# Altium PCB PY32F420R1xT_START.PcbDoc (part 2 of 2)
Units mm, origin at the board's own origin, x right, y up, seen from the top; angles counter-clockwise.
Board outline 45 x 98.2 mm, 2 copper layers (Top Layer, Bottom Layer), stack 0.533 mm thick; 144 components, 163 nets, 571 pads, 318 vias.
Unrouted connection lines stored in the file: 5.
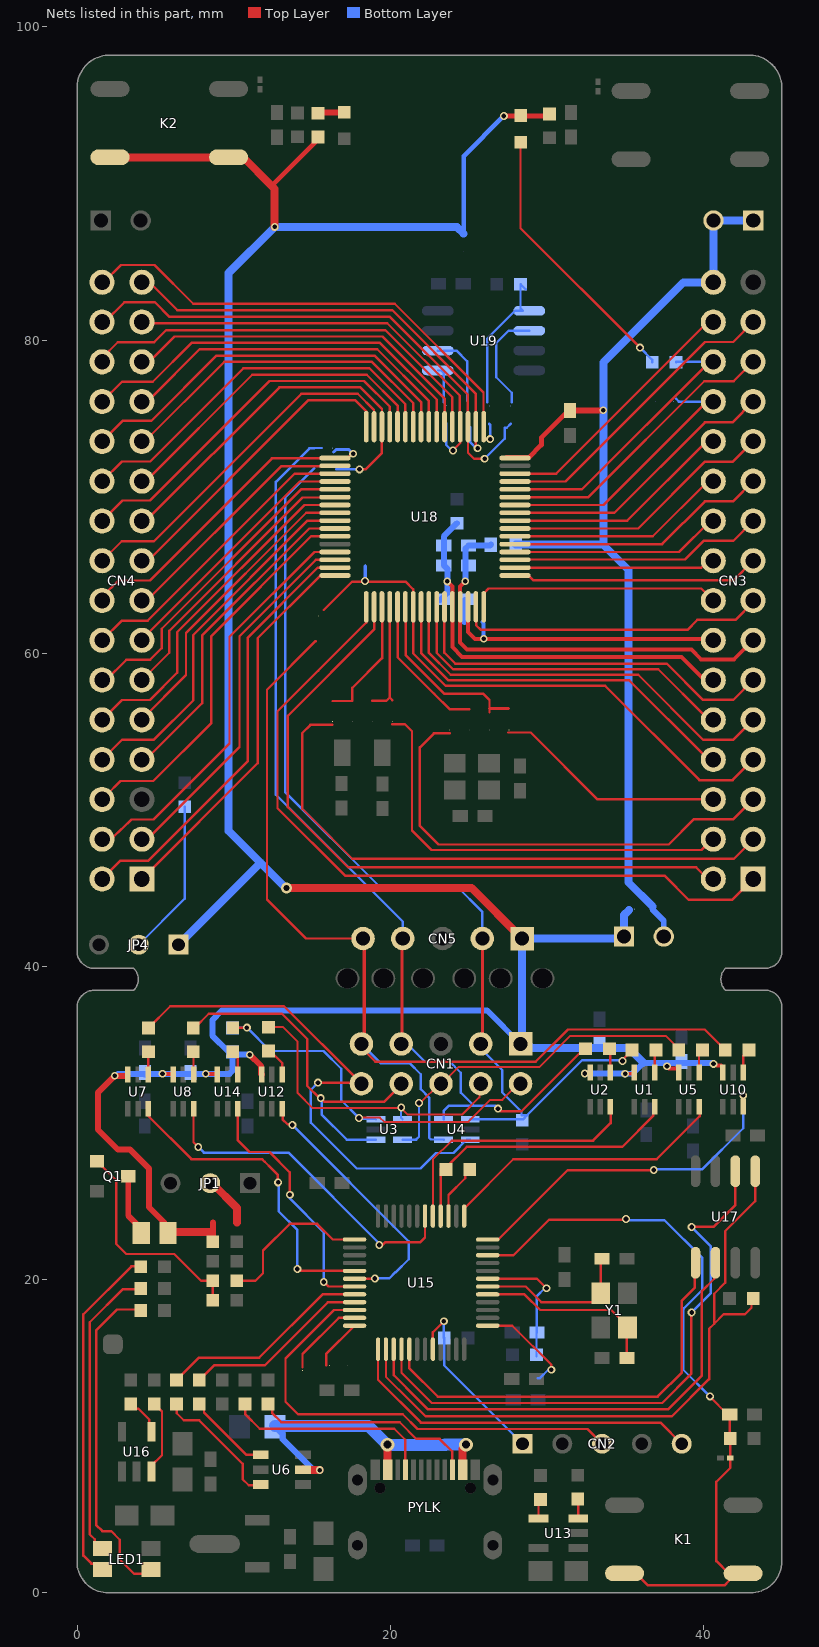
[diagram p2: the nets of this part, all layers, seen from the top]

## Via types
v1: diameter 0.5, hole 0.3, Top Layer to Bottom Layer, 156 vias
v2: diameter 0.5, hole 0.3, Top Layer to Bottom Layer, tented both sides, 134 vias
v3: diameter 0.559, hole 0.305, Top Layer to Bottom Layer, 14 vias
v4: diameter 0.889, hole 0.508, Top Layer to Bottom Layer, tented both sides, 8 vias
v5: diameter 0.762, hole 0.381, Top Layer to Bottom Layer, tented both sides, 2 vias
v6: diameter 1.016, hole 0.508, Top Layer to Bottom Layer, tented both sides, 2 vias
v7: diameter 0.61, hole 0.305, Top Layer to Bottom Layer, tented both sides, 1 vias
v8: diameter 0.711, hole 0.381, Top Layer to Bottom Layer, 1 vias

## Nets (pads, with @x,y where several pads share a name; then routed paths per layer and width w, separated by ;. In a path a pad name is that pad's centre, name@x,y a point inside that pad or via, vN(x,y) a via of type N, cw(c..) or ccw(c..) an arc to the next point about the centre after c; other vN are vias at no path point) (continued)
NetC36_2: C36.2 R63.2 | length 1.4
  Bottom Layer w0.381: R63.2@24.739,62.001 24.765,62.027 C36.2@24.765,63.398
NetJP4_2: JP4.2 R55.1 | length 10
  Bottom Layer w0.152: JP4.2@3.937,41.391 6.871,44.325 R55.1@6.871,50.202
NetLED1_2: LED1.2 R9.1 | length 21.5
  Top Layer w0.152: R9.1@4.064,18.034 4.005,18.093 2.548,18.093 1.219,16.764 1.219,4.343 1.621,3.942 2.181,3.942 2.731,3.392 2.731,2.138 3.653,1.216 4.447,1.216 LED1.2@4.725,1.494
NetLED1_3: LED1.3 R6.1 | length 22.5
  Top Layer w0.152: LED1.3@1.125,1.486 LED1.3@1.498,1.113 ; LED1.3@1.625,1.494 1.252,1.867 0.917,1.867 0.406,2.378 0.406,17.789 3.469,20.852 4.04,20.852 R6.1@4.064,20.828
NetLED1_4: LED1.4 R4.1 | length 19.2
  Top Layer w0.152: LED1.4@1.439,2.502 1.127,2.814 1.127,3.422 0.813,3.736 0.813,17.281 2.931,19.399 4.032,19.399 R4.1@4.064,19.431
NetLED_PB2_2: LED_PB2.2 R45.1 | length 17.5
  Top Layer w0.152: LED_PB2.2@28.321,92.634 28.321,87.14 v1(35.947,79.514)
  Bottom Layer w0.152: v1(35.947,79.514) 36.728,78.733 R45.1@36.728,78.588
NetLED_VDD*_1: LED_VDD*.1 R40.1 | length 1.7
  Top Layer w0.152: R40.1@15.392,94.488 R40.1@15.443,94.539
  Top Layer w0.381: R40.1@15.443,94.539 LED_VDD*.1@17.069,94.539
NetPYLK_A5: PYLK.A5 R1.2 | length 13.5
  Top Layer w0.152: R1.2@10.731,12.065 10.731,11.425 11.672,10.485 20.259,10.485 20.964,9.78 20.964,7.888 PYLK.A5@20.98,7.871
NetPYLK_B5: PYLK.B5 R3.1 | length 14.4
  Top Layer w0.152: R3.1@12.192,12.065 12.454,11.803 12.454,11.489 13.052,10.891 20.602,10.891 21.658,9.836 23.153,9.836 23.957,9.033 23.957,7.895 PYLK.B5@23.98,7.871
NetQ1_1: Q1.1 R19.1 R20.2 | length 14.2
  Top Layer w0.152: Q1.1@1.27,27.554 1.32,27.554 1.618,27.256 1.618,27.209 2.501,26.327 2.501,22.284 3.146,21.639 6.209,21.639 7.915,19.933 R19.1@8.675,19.933 ; R20.2@8.675,18.691 R19.1@8.675,19.933
NetQ1_3: Q1.3 R15.1 | length 4.2
  Top Layer w0.152: Q1.3@3.187,26.521 Q1.3@3.27,26.604 ; R15.1@4.103,22.987 R15.1@4.103,23.137
  Top Layer w0.381: Q1.3@3.27,26.604 3.27,24.086 4.103,23.253 R15.1@4.103,22.987
NetR2_1: R2.1 U1.4 | length 1.5
  Top Layer w0.152: U1.4@36.887,33.231 36.887,34.595 R2.1@36.962,34.671
NetR7_1: R7.1 U2.4 | length 1.5
  Top Layer w0.152: R7.1@33.987,34.671 34.056,34.602 U2.4@34.056,33.231
NetR10_1: R10.1 U5.4 | length 1.5
  Top Layer w0.152: U5.4@39.717,33.231 39.717,34.45 R10.1@39.938,34.671
NetR11_1: R11.1 U6.3 | length 8.5
  Top Layer w0.152: R11.1@6.35,12.065 6.37,12.045 6.37,11.473 6.818,11.025 7.793,11.025 10.572,8.245 10.572,7.261 10.963,6.87 11.677,6.87 U6.3@11.723,6.916
NetR12_1: R12.1 U6.1 | length 5.8
  Top Layer w0.152: R12.1@7.842,12.192 8.106,11.928 8.106,11.523 10.82,8.809 U6.1@11.988,8.809
NetR13_1: R13.1 U7.4 | length 1.5
  Top Layer w0.152: R13.1@4.408,34.544 4.55,34.402 U7.4@4.55,33.104
NetR14_1: R14.1 U8.4 | length 1.5
  Top Layer w0.152: R14.1@7.136,34.544 R14.1@7.387,34.294 ; U8.4@7.439,33.104 R14.1@7.439,34.293
NetR18_1: R18.1 U10.4 | length 1.6
  Top Layer w0.152: U10.4@42.547,33.231 42.547,34.305 R18.1@42.913,34.671
NetR22_1: R22.1 U12.4 | length 1.9
  Top Layer w0.152: R22.1@12.233,34.598 12.335,34.598 13.099,33.833 U12.4@13.099,33.104
NetR24_2: R24.2 U13.4 | length 1.3
  Top Layer w0.152: U13.4@29.464,4.763 29.464,5.842 R24.2@29.591,5.969
NetR25_2: R25.2 U13.3 | length 1.2
  Top Layer w0.152: U13.3@32.004,4.763 R25.2@32.004,5.969
NetR26_1: R26.1 U14.4 | length 1.6
  Top Layer w0.152: R26.1@9.936,34.562 10.269,34.229 U14.4@10.269,33.104
NetR27_2: R27.2 U15.1 | length 6.5
  Top Layer w0.152: U15.1@26.221,17.062 27.792,17.062 30.288,14.566 v1(30.288,14.246)
  Bottom Layer w0.152: 29.422,13.712 29.556,13.712 30.09,14.246 v1(30.288,14.246)
NetR29_2: R29.2 U16.4 | length 2.4
  Top Layer w0.152: R29.2@3.429,12.065 3.734,11.76 3.923,11.76 4.61,11.073 4.61,10.439 U16.4@4.763,10.287
NetR30_2: R30.2 U16.3 | length 4.8
  Top Layer w0.152: U16.3@4.763,7.747 4.763,8.128 5.424,8.79 5.424,11.574 5.258,11.741 5.258,11.76 R30.2@4.953,12.065
NetR31_1: R31.1 U15.36 | length 3.3
  Top Layer w0.152: 15.906,14.522 15.906,15.247 U15.36@17.721,17.062
NetR33_1: R33.1 U15.35 | length 5.1
  Top Layer w0.152: 14.401,14.412 14.401,15.25 16.713,17.562 U15.35@17.721,17.562
NetR44_1: R44.1 R46.1 U19.1 | length 9.3
  Bottom Layer w0.152: 26.187,76.023 26.187,80.08 27.972,81.864 28.473,81.864 28.321,82.017 R44.1@28.321,83.566 ; R44.1@28.325,83.557 R44.1@28.651,83.231
NetR47_1: R47.1 U19.2 | length 6.6
  Bottom Layer w0.152: 27.762,76.022 27.762,76.632 26.772,77.622 26.772,79.807 27.559,80.594 U19.2@28.88,80.594
NetR48_2: R48.2 U19.6 | length 4.7
  Bottom Layer w0.152: U19.6@23.038,79.324 24.232,79.324 24.917,78.638 24.917,76.124
NetR49_2: R49.2 U19.5 | length 2.3
  Bottom Layer w0.152: U19.5@23.038,78.054 23.266,78.054 23.419,77.901 23.419,76.022
OSC_32INa: R38.2 R57.2 U18.3 | length 8.1
  Top Layer w0.152: 16.312,56.951 17.585,56.951 17.585,57.793 19.482,59.69 19.482,62.952 U18.3@19.468,62.967
OSC_32OUTa: R39.2 R59.2 U18.4 | length 7.2
  Top Layer w0.152: 18.847,56.964 19.757,56.964 19.965,57.173 ; U18.4@19.965,62.967 19.965,57.173 ; 20.137,57.001 19.965,57.173
OSC_INa: R41.2 R53.2 U18.5 | length 9.2
  Top Layer w0.152: U18.5@20.469,63.015 20.469,59.745 22.811,57.403 23.806,56.408 23.817,56.418 25.043,56.418
OSC_OUTa: R42.2 R56.2 U18.6 | length 11.7
  Top Layer w0.152: U18.6@20.98,63.008 20.98,59.881 23.455,57.405 25.954,57.405 26.34,57.018 R56.2@26.34,56.236
  Top Layer w0.203: 26.341,56.469 26.347,56.463 27.533,56.463
PA0: CN3.14 R63.1 U18.14 | length 18.6
  Top Layer w0.254: U18.14@24.969,62.952 24.969,61.342 25.411,60.9 40.557,60.9 CN3.14@40.63,60.827
  Bottom Layer w0.254: R63.1@25.876,62.001 25.97,61.908 v1(25.97,60.925)
PA1: CN3.15 U18.15 | length 19.8
  Top Layer w0.152: U18.15@25.468,62.967 25.486,62.948 25.486,61.791 25.786,61.492 38.972,61.492 39.609,62.128 42.041,62.128 43.17,63.257 CN3.15@43.17,63.367
PA2: CN3.16 U18.16 | length 16
  Top Layer w0.152: U18.16@25.968,62.967 25.968,63.821 26.282,64.135 39.862,64.135 CN3.16@40.63,63.367
PA3: CN3.17 U18.17 | length 15.9
  Top Layer w0.152: U18.17@27.967,64.966 28.836,64.966 29.152,64.65 41.913,64.65 CN3.17@43.17,65.907
PA4: CN3.20 U18.20 | length 13.2
  Top Layer w0.152: U18.20@28.271,66.467 38.448,66.467 40.429,68.447 CN3.20@40.63,68.447
PA5: CN3.21 U18.21 | length 16.6
  Top Layer w0.152: U18.21@28.271,66.966 37.363,66.966 40.094,69.698 41.88,69.698 CN3.21@43.17,70.987
PA6: CN3.22 U18.22 | length 13.8
  Top Layer w0.152: U18.22@28.271,67.467 36.761,67.467 40.282,70.987 CN3.22@40.63,70.987
PA7: CN3.23 U18.23 | length 17.2
  Top Layer w0.152: U18.23@28.271,67.966 35.834,67.966 40.106,72.238 41.88,72.238 CN3.23@43.17,73.527
PA8: CN4.24 U18.41 | length 25.4
  Top Layer w0.152: CN4.24@1.604,73.527 2.914,74.838 4.74,74.838 8.909,79.007 19.005,79.007 21.973,76.039 21.973,74.471 U18.41@21.968,74.466
PA9: CN4.23 U18.42 | length 22.1
  Top Layer w0.152: CN4.23@4.141,73.527 4.232,73.437 9.396,78.6 18.837,78.6 21.476,75.961 21.476,74.475 U18.42@21.468,74.466
PA10: CN4.22 U18.43 | length 24.8
  Top Layer w0.152: CN4.22@1.604,70.987 2.862,72.246 4.676,72.246 10.624,78.194 18.668,78.194 20.953,75.909 20.953,74.481 U18.43@20.968,74.466 ; U18.43@20.94,74.422 U18.43@20.976,74.458
PA11: CN4.21 U18.44 | length 21.7
  Top Layer w0.152: CN4.21@4.409,70.72 CN4.21@4.141,70.987 4.184,71.03 4.432,71.03 11.19,77.787 18.5,77.787 20.47,75.817 U18.44@20.47,74.498
PA12: CN4.20 U18.45 | length 24
  Top Layer w0.152: CN4.20@1.604,68.447 2.908,69.751 4.668,69.751 12.297,77.381 18.332,77.381 19.966,75.746 U18.45@19.966,74.466
PA13: CN4.19 R51.2 U18.46 | length 25.6
  Top Layer w0.152: CN4.19@4.141,68.447 4.163,68.469 4.414,68.469 12.92,76.975 18.092,76.975 19.474,75.592 U18.46@19.474,74.473 ; v2(18.034,71.743) 18.417,71.743 19.468,72.793 U18.46@19.468,74.466
  Bottom Layer w0.152: 16.547,71.743 v2(18.034,71.743)
PA14: CN4.16 R52.2 U18.49 | length 21.4
  Top Layer w0.152: CN4.16@1.604,63.367 1.604,63.608 2.64,64.645 4.65,64.645 12.446,72.441 15.149,72.441 ; 15.149,72.448 U18.49@15.915,72.448 ; U18.49@15.936,72.448 U18.49@16.468,72.448 ; U18.49@16.468,72.467 17.284,72.467 17.552,72.735 v1(17.629,72.735)
  Bottom Layer w0.203: 16.383,72.847 16.545,73.009 17.354,73.009 v1(17.629,72.735)
PA15: CN4.15 U18.50 | length 16.2
  Top Layer w0.152: CN4.15@4.141,63.367 4.455,63.367 13.022,71.933 15.82,71.933 15.835,71.948 16.753,71.948 U18.50@16.772,71.966
PB0: CN3.26 R58.2 U18.26 | length 17.6
  Top Layer w0.152: U18.26@27.949,69.448 U18.26@27.967,69.467 ; U18.26@28.271,69.467 33.627,69.467 40.228,76.067 CN3.26@40.63,76.067
  Bottom Layer w0.152: 38.258,76.247 38.413,76.092 ; 38.413,76.067 CN3.26@40.63,76.067
PB1: CN3.27 U18.27 | length 18.5
  Top Layer w0.152: U18.27@28.271,69.966 32.654,69.966 40.051,77.364 41.926,77.364 CN3.27@43.17,78.607
PB2: CN3.28 R45.2 U18.28 | length 18.1
  Top Layer w0.152: U18.28@28.271,70.467 32.24,70.467 40.38,78.607 CN3.28@40.63,78.607
  Bottom Layer w0.152: R45.2@38.252,78.588 38.272,78.607 CN3.28@40.63,78.607
PB3: CN4.10 U18.55 | length 22.1
  Top Layer w0.152: CN4.10@1.604,55.747 2.874,57.017 4.656,57.017 6.401,58.762 6.401,61.349 14.519,69.467 U18.55@16.468,69.467
PB4: CN4.9 U18.56 | length 19.7
  Top Layer w0.152: CN4.9@4.141,55.747 4.141,55.787 6.957,58.603 6.957,61.291 14.632,68.966 U18.56@16.772,68.966
PB5: CN4.8 U18.57 | length 23.9
  Top Layer w0.152: CN4.8@1.604,53.207 1.839,53.443 2.884,54.487 4.919,54.487 7.419,56.987 7.419,61.162 14.724,68.467 U18.57@16.772,68.467
PB6: CN4.7 U18.58 | length 21.3
  Top Layer w0.152: CN4.7@4.141,53.207 4.384,53.207 7.987,56.809 7.987,61.123 14.83,67.966 U18.58@16.772,67.966
PB7: CN4.6 U18.59 | length 25.4
  Top Layer w0.152: CN4.6@1.604,50.667 1.871,50.934 2.779,51.842 4.865,51.842 8.577,55.554 8.577,61.097 14.946,67.467 U18.59@16.772,67.467
PB8: CN4.4 U18.61 | length 26.7
  Top Layer w0.152: CN4.4@1.604,48.127 1.731,48.254 2.301,48.254 3.483,49.385 4.888,49.385 9.738,54.236 9.738,61.049 15.156,66.467 U18.61@16.772,66.467
PB9: CN4.3 U18.62 | length 24.2
  Top Layer w0.152: CN4.3@4.141,48.127 4.409,48.394 4.755,48.394 10.371,54.011 10.371,61.082 15.255,65.966 U18.62@16.772,65.966
PB10: CN3.29 U18.29 | length 19.1
  Top Layer w0.152: U18.29@28.271,70.966 31.19,70.966 40.101,79.877 41.9,79.877 CN3.29@43.17,81.147
PB11: CN3.30 U18.30 | length 16.4
  Top Layer w0.152: U18.30@28.271,71.467 30.598,71.467 40.278,81.147 CN3.30@40.63,81.147
PB12: CN4.32 R46.2 U18.33 | length 32.6
  Top Layer w0.152: CN4.32@1.604,83.687 1.712,83.687 2.816,84.792 4.949,84.792 7.423,82.318 20.292,82.318 25.952,76.658 25.952,74.482 U18.33@25.968,74.466 25.931,74.43 25.931,73.678 v1@26.373,73.678
  Bottom Layer w0.152: R46.2@26.315,74.644 26.38,74.579 v1(26.38,73.672)
PB13: CN4.31 R48.1 U18.34 | length 29.4
  Top Layer w0.152: CN4.31@4.141,83.687 4.345,83.484 4.832,83.484 6.405,81.911 20.124,81.911 25.45,76.585 25.45,74.483 U18.34@25.468,74.466 25.468,73.108 25.485,73.091 v1(25.582,73.091)
  Bottom Layer w0.152: 25.121,74.422 25.121,73.456 25.485,73.091 v1(25.582,73.091)
PB14: CN4.30 R47.2 U18.35 | length 34.2
  Top Layer w0.152: CN4.30@1.604,81.147 1.754,81.147 3.021,82.414 4.97,82.414 5.906,81.478 19.982,81.478 24.959,76.502 U18.35@24.959,74.475 ; U18.35@24.968,74.466 24.968,72.806 25.355,72.42 v1(26.026,72.42)
  Bottom Layer w0.152: v1(26.026,72.42) 27.305,73.699 27.305,74.397 27.439,74.397 R47.2@27.687,74.644
PB15: CN4.29 R49.1 U18.36 | length 27.9
  Top Layer w0.152: CN4.29@4.141,81.147 4.217,81.072 19.814,81.072 24.447,76.438 24.447,75.405 24.449,75.403 24.449,74.485 U18.36@24.468,74.466 24.468,73.429 24.003,72.964 v1(24.003,72.944)
  Bottom Layer w0.152: R49.1@23.571,74.676 23.571,73.305 23.931,72.944 v1(24.003,72.944)
PC0: CN3.8 U18.8 | length 24.4
  Top Layer w0.152: U18.8@21.97,62.964 21.97,60.013 23.714,58.27 35.265,58.27 40.129,53.405 40.432,53.405 CN3.8@40.63,53.207
PC1: CN3.9 U18.9 | length 26.4
  Top Layer w0.152: U18.9@22.468,62.905 22.468,60.019 23.861,58.625 35.832,58.625 39.989,54.469 41.891,54.469 CN3.9@43.17,55.747
PC2: CN3.10 U18.10 | length 22.3
  Top Layer w0.152: U18.10@22.968,62.926 22.968,60.021 24.008,58.981 37.116,58.981 40.162,55.935 40.442,55.935 CN3.10@40.63,55.747
PC3: CN3.11 U18.11 | length 24.4
  Top Layer w0.152: U18.11@23.457,62.956 23.457,60.035 24.156,59.336 37.656,59.336 39.973,57.019 41.902,57.019 CN3.11@43.17,58.287
PC4: CN3.24 U18.24 | length 14.5
  Top Layer w0.152: U18.24@28.271,68.467 35.131,68.467 40.192,73.527 CN3.24@40.63,73.527
PC5: CN3.25 U18.25 | length 17.8
  Top Layer w0.152: U18.25@28.271,68.966 34.315,68.966 40.091,74.742 41.845,74.742 CN3.25@43.17,76.067
PC6: CN4.28 U18.37 | length 27
  Top Layer w0.152: CN4.28@1.604,78.607 1.604,78.861 2.599,79.856 4.919,79.856 5.695,80.632 19.679,80.632 23.968,76.343 U18.37@23.968,74.466
PC7: CN4.27 U18.38 | length 23.4
  Top Layer w0.152: CN4.27@4.141,78.607 4.602,78.607 6.22,80.226 19.51,80.226 23.469,76.267 U18.38@23.469,74.468
PC8: CN4.26 U18.39 | length 26.1
  Top Layer w0.152: CN4.26@1.604,76.067 2.876,77.339 4.837,77.339 7.317,79.819 19.342,79.819 22.967,76.195 U18.39@22.967,74.467
PC9: CN4.25 U18.40 | length 22.7
  Top Layer w0.152: CN4.25@4.141,76.067 4.378,76.303 4.716,76.303 7.825,79.413 19.174,79.413 22.449,76.138 22.449,75.403 22.449,74.485 U18.40@22.468,74.466
PC10: CN4.14 U18.51 | length 19.3
  Top Layer w0.152: CN4.14@1.604,60.827 2.863,62.086 4.518,62.086 13.898,71.467 U18.51@16.468,71.467
PC11: CN4.13 U18.52 | length 16.6
  Top Layer w0.152: CN4.13@4.141,60.827 4.141,60.89 14.219,70.967 U18.52@16.467,70.967
PC12: CN4.12 U18.53 | length 20.9
  Top Layer w0.152: CN4.12@1.604,58.287 1.853,58.287 3.153,59.587 4.664,59.587 5.406,60.329 5.406,61.562 14.308,70.464 U18.53@16.769,70.464
PC13: CN3.2 U18.2 | length 44.1
  Top Layer w0.152: U18.2@18.972,62.891 18.972,61.517 13.455,56 13.455,50.177 17.301,46.331 39.534,46.331 40.278,45.587 CN3.2@40.63,45.587
PC14: CN3.3 R38.1 | length 37.6
  Top Layer w0.152: 16.312,55.427 14.9,55.427 14.376,54.904 14.376,50.071 17.575,46.873 41.952,46.873 43.17,48.091 CN3.3@43.17,48.127
PC15: CN3.4 R39.1 | length 27.8
  Top Layer w0.152: 20.137,55.477 20.929,55.477 21.387,55.019 21.387,48.685 22.639,47.433 39.869,47.433 40.564,48.127 CN3.4@40.63,48.127
PD0: CN3.5 R41.1 | length 30.3
  Top Layer w0.152: 23.806,54.884 22.788,54.884 21.89,53.986 21.89,48.978 23.08,47.788 26.999,47.788 37.781,47.788 39.403,49.41 41.913,49.41 CN3.5@43.17,50.667
PD1: CN3.6 R42.1 | length 14.9
  Top Layer w0.152: 27.533,54.939 28.972,54.939 33.243,50.667 CN3.6@40.63,50.667
PD2: CN4.11 U18.54 | length 18.3
  Top Layer w0.152: CN4.11@4.144,58.287 4.256,58.399 5.885,60.029 5.885,61.43 14.402,69.947 15.834,69.947 15.835,69.948 16.753,69.948 U18.54@16.772,69.966
PD4: CN3.18 U18.18 | length 12.5
  Top Layer w0.152: U18.18@28.274,65.464 39.848,65.464 40.292,65.907 CN3.18@40.63,65.907
PD5: CN3.19 U18.19 | length 15.9
  Top Layer w0.152: U18.19@28.271,65.966 28.29,65.985 38.811,65.985 40.003,67.177 41.9,67.177 CN3.19@43.17,68.447
PD6: CN4.18 U18.47 | length 23.3
  Top Layer w0.152: CN4.18@1.604,65.907 2.851,67.154 4.914,67.154 14.328,76.568 17.923,76.568 18.964,75.528 U18.47@18.964,74.46
PD7: CN4.17 U18.48 | length 19.8
  Top Layer w0.152: CN4.17@4.141,65.907 4.529,65.907 14.783,76.162 17.755,76.162 18.478,75.439 U18.48@18.478,74.547
PD8: CN4.2 U18.63 | length 28
  Top Layer w0.152: CN4.2@1.604,45.587 2.779,46.762 4.558,46.762 10.912,53.116 10.912,61.005 15.374,65.467 U18.63@16.772,65.467
PD9: CN4.1 U18.64 | length 25.3
  Top Layer w0.152: CN4.1@4.141,45.587 11.533,52.979 11.533,60.958 15.541,64.966 U18.64@16.772,64.966
PD10: CN3.1 U18.1 | length 48.6
  Top Layer w0.152: U18.1@18.466,62.965 18.466,61.956 15.392,58.882 12.802,56.292 12.802,50.107 17.111,45.798 37.512,45.798 39.06,44.249 41.832,44.249 CN3.1@43.17,45.587
PD11: CN3.7 R54.2 R62.2 U18.7 | length 37.3
  Top Layer w0.152: 15.759,62.76 17.57,64.571 20.973,64.571 21.468,64.076 U18.7@21.468,62.967 21.467,59.992 23.546,57.914 33.724,57.914 39.74,51.898 41.86,51.898 CN3.7@43.17,53.207
  Bottom Layer w0.203: v1(18.384,64.609) 18.4,64.625 18.4,65.549
PYLK_BOOT0: CN2.1 R28.1 U15.44 | length 12
  Top Layer w0.152: U15.44@22.721,15.562 22.721,16.639 v2(23.424,17.342)
  Bottom Layer w0.152: v2(23.424,17.342) 23.424,16.301 R28.1@23.444,16.281 23.444,14.529 CN2.1@28.448,9.525
PYLK_KEY: C6.2 K1.1 K1.2 R16.1 U11.1 U15.10 | length 47
  Top Layer w0.152: U15.10@26.221,21.562 27.867,21.562 30.136,23.83 35.006,23.83 v2(35.052,23.876) ; K1.2@34.964,1.245 35.693,1.245 36.462,0.476 41.335,0.476 41.631,0.772 41.631,0.877 K1.1@41.999,1.245 ; v2(40.411,12.548) 40.411,12.522 41.554,11.379 C6.2@41.656,11.379 ; C6.2@41.681,11.379 41.681,9.881 R16.1@41.707,9.855 41.714,9.848 U11.1@41.714,8.611 41.714,7.983 40.825,7.094 40.825,2.032 41.613,1.245 K1.1@41.999,1.245 ; K1.1@42.533,1.245 K1.1@41.999,1.245
  Bottom Layer w0.152: v2(35.052,23.876) 35.13,23.798 35.373,23.798 35.374,23.797 37.507,23.797 39.929,21.374 39.929,19.355 38.742,18.168 38.742,18.154 38.714,18.126 38.714,14.245 v2(40.411,12.548)
PYLK_NRST: C24.2 R36.1 U15.7 | length 8.7
  Top Layer w0.152: U15.7@26.221,20.062 29.372,20.062 v2(29.982,19.451)
  Bottom Layer w0.152: R36.1@29.34,15.113 29.34,16.612 C24.2@29.365,16.637 29.365,18.948 29.868,19.451 v2(29.982,19.451)
PYLK_OSCIN: C19.2 U15.5 Y1.3 | length 11.8
  Top Layer w0.152: U15.5@26.221,19.062 28.576,19.062 29.576,18.062 34.115,18.062 35.143,17.034 Y1.3@35.143,16.934 35.106,16.897 C19.2@35.106,14.986
PYLK_OSCOUT: C25.2 U15.6 Y1.1 | length 10.2
  Top Layer w0.152: U15.6@26.221,19.562 28.651,19.562 29.651,18.562 32.945,18.562 33.443,19.06 Y1.1@33.443,19.134 33.443,21.248 C25.2@33.531,21.336
PYLK_SPI_CS: R35.1 U15.38 U17.1 | length 42.4
  Top Layer w0.127: U15.38@19.721,15.562 19.721,13.808 21.277,12.252
  Top Layer w0.152: 21.277,12.252 22.249,11.28 37.986,11.28 40.358,13.652 40.358,16.863 40.685,17.19 ; R35.1@43.18,18.796 43.069,18.685 43.069,18.204 42.656,17.791 41.286,17.791 40.685,17.19 ; U17.1@43.307,26.924 43.307,25.019 41.394,23.106 41.394,19.812 40.685,19.103 40.685,17.19
PYLK_SPI_MISO: U15.40 U17.2 | length 37.5
  Top Layer w0.152: U15.40@20.721,15.562 20.721,14.054 22.652,12.123 37.363,12.123 39.215,13.975 39.215,17.879 v2(39.243,17.907) ; v2(39.243,23.368) 40.64,23.368 42.037,24.765 U17.2@42.037,26.924
  Bottom Layer w0.152: v2(39.243,17.907) 40.458,19.122 40.458,22.153 v2(39.243,23.368)
PYLK_SPI_MOSI: U15.41 U17.5 | length 27.4
  Top Layer w0.152: U15.41@21.221,15.562 21.221,14.338 23.029,12.53 37.069,12.53 38.622,14.082 38.622,18.671 39.45,19.499 39.45,21.035 U17.5@39.497,21.082
PYLK_SPI_SCK: U15.39 U17.6 | length 30.7
  Top Layer w0.152: U15.39@20.221,15.562 20.221,13.903 21.751,12.373 22.407,11.717 37.746,11.717 39.883,13.854 39.883,19.255 40.689,20.061 40.689,21.004 U17.6@40.767,21.082
SWD_SCK: CN2.5 U15.37 | length 23
  Top Layer w0.152: U15.37@19.221,15.562 19.221,13.608 21.958,10.871 34.722,10.871 37.262,10.871 CN2.5@38.608,9.525
SWD_SDA: CN2.3 U15.34 | length 29.8
  Top Layer w0.152: U15.34@17.721,18.062 16.411,18.062 13.311,14.962 13.311,12.21 14.111,11.41 20.796,11.41 21.741,10.465 30.048,10.465 32.588,10.465 CN2.3@33.528,9.525
T_RESET: CN1.9 CN5.5 R18.2 R54.1 U4.4 | length 66.5
  Top Layer w0.152: 15.235,60.777 12.129,57.671 12.129,44.267 14.613,41.783 CN5.5@18.261,41.783 ; CN1.9@18.359,34.615 19.055,33.918 29.284,33.918 31.343,35.978 40.083,35.978 R18.2@41.389,34.671
  Top Layer w0.203: CN1.9@18.339,35.23 CN5.5@18.339,41.575
  Bottom Layer w0.152: CN5.5@18.261,41.783 CN5.5@18.44,41.604 ; CN1.9@18.44,35.331 CN1.9@18.161,35.052 19.386,33.827 21.235,33.827 21.948,33.114 21.948,32.167 22.483,31.632 22.483,29.065 22.596,28.952 23.396,28.952 U4.4@23.407,28.941
T_RESETa: U10.3 U15.12 | length 22.1
  Top Layer w0.152: U15.12@26.221,22.562 26.893,22.562 31.33,26.999 33.567,26.999 v2(36.828,26.999) ; v2(42.54,31.768) 42.547,31.761 U10.3@42.547,31.031
  Bottom Layer w0.152: v2(36.828,26.999) 36.872,27.043 39.914,27.043 42.54,29.67 v2(42.54,31.768)
T_RTCK_DTRa: U5.3 U15.13 | length 18.6
  Top Layer w0.152: U15.13@24.721,24.062 24.721,24.551 27.856,27.686 37.008,27.686 39.756,30.434 39.756,30.992 U5.3@39.717,31.031
T_RTCK_VCP_DTR: CN1.6 R10.2 U3.5 | length 22.1
  Top Layer w0.127: v2(21.839,31.284) 21.926,31.284 23.154,32.512 CN1.6@23.241,32.512 23.282,32.512 24.346,33.575 29.508,33.575 31.504,35.571 37.592,35.571 38.109,35.054 38.109,34.976 R10.2@38.414,34.671
  Bottom Layer w0.152: U3.5@20.789,28.941 21.654,28.941 21.839,29.126 v2(21.839,31.284)
T_TCK_SWCLK: CN1.7 CN5.4 R7.2 R52.1 U4.5 | length 61.6
  Top Layer w0.152: CN1.7@20.828,35.306 CN1.7@20.862,35.34 ; CN5.4@20.828,41.783 CN5.4@20.862,41.749 ; v2(26.886,30.92) 27.055,30.751 28.371,30.751 32.29,34.671 R7.2@32.463,34.671
  Top Layer w0.203: CN1.7@20.755,35.106 CN5.4@20.755,41.591
  Bottom Layer w0.152: 15.162,73.082 14.84,73.082 12.7,70.942 12.7,50.969 20.801,42.868 CN5.4@20.801,41.783 CN5.4@20.828,41.756 ; R52.1@15.17,73.101 15.628,73.102 ; CN1.7@20.701,35.052 20.828,35.179 CN1.7@20.828,35.242 ; CN1.7@20.891,35.242 22.237,33.897 23.816,33.897 24.501,33.212 24.501,31.942 25.327,31.115 ; U4.5@23.407,30.241 23.407,30.773 23.749,31.115 25.327,31.115 ; v2(26.886,30.92) 26.691,31.115 25.327,31.115
T_TCK_SWCLKa: U2.3 U15.17 | length 17
  Top Layer w0.127: U15.17@22.721,24.062 22.721,27.68 23.921,28.88
  Top Layer w0.152: 23.921,28.88 26.61,28.88 32.955,28.88 34.072,29.997 34.072,31.016 U2.3@34.056,31.031
T_TDI_VCP_TX: CN1.4 R22.2 U3.4 | length 19.9
  Top Layer w0.127: R22.2@12.233,36.122 13.155,36.122 14.085,35.191 14.085,31.918 15.044,30.959 v2@20.701,30.959 ; R22.2@12.233,36.198 R22.2@12.272,36.16 ; v2@20.702,30.959 21.127,30.534 24.581,30.534 25.694,31.646 25.694,32.425 CN1.4@25.781,32.512
  Bottom Layer w0.127: v2@20.702,30.987 20.702,30.328 U3.4@20.789,30.241
  other v2: 20.701,30.988
T_TDI_VCP_TXa: U12.3 U15.30 | length 17.1
  Top Layer w0.152: U12.3@13.099,30.904 13.13,30.873 13.13,30.235 13.443,29.923 13.705,29.923 v2(13.749,29.878) ; U15.30@17.721,20.062 19,20.062 v2(19.018,20.081)
  Bottom Layer w0.152: v2(13.749,29.878) 21.186,22.442 21.186,21.308 20.36,20.482 20.338,20.482 19.937,20.081 v2(19.018,20.081)
T_TDO_SWO: CN1.10 R13.2 U4.3 | length 33.9
  Top Layer w0.152: R13.2@4.563,36.07 5.956,37.462 13.211,37.462 CN1.10@17.996,32.677 ; v2(15.389,32.582) 15.406,32.565 17.884,32.565 CN1.10@17.996,32.677 ; CN1.10@18.161,32.512 CN1.10@17.996,32.677
  Bottom Layer w0.152: v2(15.389,32.582) 14.931,32.124 14.931,30.025 17.858,27.098 21.928,27.098 22.921,28.092 24.04,28.092 24.889,28.941 U4.3@25.107,28.941 U4.3@25.048,28.882
T_TDO_SWOa: U7.3 U15.29 | length 20.5
  Top Layer w0.152: U7.3@4.55,30.904 4.55,30.451 7.301,27.7 11.813,27.7 11.979,27.534 11.989,27.534 12.421,27.102 12.421,27.092 12.825,26.688 12.825,26.23 v2(12.843,26.213) ; v2(14.069,20.684) 14.191,20.562 16.295,20.562 U15.29@17.721,20.562
  Bottom Layer w0.152: v2(12.843,26.213) 12.876,26.179 12.876,24.357 14.069,23.165 v2(14.069,20.684)
T_TMS_SWDIO: CN1.3 CN5.2 R2.2 R5.2 R51.1 U4.1 | length 63.8
  Top Layer w0.152: CN5.2@25.738,41.953 25.908,41.783 CN5.2@25.892,41.767 ; CN1.3@25.892,34.701 CN1.3@26.049,34.544 ; v2@34.839,33.913 34.839,34.048 35.133,34.342 35.133,34.366 R2.2@35.438,34.671
  Top Layer w0.203: CN1.3@25.889,35.16 CN5.2@25.889,41.645
  Bottom Layer w0.152: 15.163,71.831 13.284,69.952 13.284,51.136 19.234,45.187 24.181,45.187 25.881,43.486 CN5.2@25.881,41.783 CN5.2@25.883,41.781 ; U4.1@25.115,30.233 28.481,30.233 R5.2@28.753,30.505 ; CN1.3@25.781,35.052 CN1.3@25.883,35.154 ; CN1.3@25.999,34.536 27.149,33.386 27.149,31.95 28.379,30.721 28.379,30.505 R5.2@28.753,30.505 ; v2(34.834,33.962) 34.779,34.017 32.264,34.017 R5.2@28.753,30.505
T_TMS_SWDIOa: R32.1 U1.3 U15.16 | length 18.4
  Top Layer w0.152: U15.16@23.221,24.062 R32.1@23.221,27.111 ; R32.1@23.558,27.035 23.558,27.152 24.895,28.49 26.332,28.49 34.829,28.49 36.788,30.449 36.788,30.932 U1.3@36.887,31.031
T_TMS_SWDIOa_OUT: R32.2 U15.15 | length 3.6
  Top Layer w0.152: U15.15@23.721,24.062 23.721,25.416 24.786,26.481 R32.2@24.786,27.258
T_TRST_RTSa: U8.3 U15.18 | length 21.3
  Top Layer w0.152: U8.3@7.439,30.904 7.439,28.775 v2(7.742,28.471) ; v2(19.302,22.209) 19.401,22.109 19.673,22.381 21.905,22.381 22.221,22.697 U15.18@22.221,24.062
  Bottom Layer w0.152: v2(7.742,28.471) 8.098,28.115 13.504,28.115 19.302,22.317 v2(19.302,22.209)
T_TRST_VCP_RTS: CN1.8 R14.2 U3.1 | length 23.7
  Top Layer w0.152: R14.2@7.424,36.071 7.507,36.071 8.413,36.977 13.087,36.977 14.696,35.369 14.696,32.374 15.479,31.591 v2(15.567,31.591) 15.789,31.369 19.626,31.369 20.828,32.571 CN1.8@20.828,32.766
  Bottom Layer w0.152: v2(15.567,31.591) 15.621,31.537 15.621,30.546 17.226,28.941 U3.1@19.089,28.941
T_VCP_RX: CN1.2 R23.1 R26.2 U3.3 | length 25.4
  Top Layer w0.127: v2(18.008,30.321) 18.04,30.353 19.34,30.353 19.62,30.073 24.991,30.073 26.398,31.48 27.162,31.48 CN1.2@28.448,32.766
  Top Layer w0.152: R26.2@9.936,36.086 10.838,36.086 v1(10.846,36.093) ; R26.2@9.936,36.369 R26.2@9.94,36.372
  Bottom Layer w0.152: R23.1@9.931,36.068 9.957,36.093 v1(10.846,36.093) 12.337,34.602 15.729,34.602 16.867,33.465 16.867,31.462 v2(18.008,30.321) 17.989,30.302 17.989,30.271 19.059,30.271 U3.3@19.089,30.241
T_VCP_RXa: U14.3 U15.31 | length 16.2
  Top Layer w0.152: U14.3@10.269,30.904 10.269,28.887 11.005,28.151 12.282,28.151 13.574,26.859 13.574,25.435 v2(13.589,25.42) ; v2(15.758,19.857) 16.053,19.562 U15.31@17.721,19.562
  Bottom Layer w0.152: v2(13.589,25.42) 13.589,25.182 15.758,23.013 v2(15.758,19.857)
TVDD: C12.2 C13.2 C14.2 C15.2 CN1.1 CN5.1 JP2.1 JP4.1 K2.1 K2.2 LED_PB2.1 R15.2 R17.2 R23.2 R34.2 R37.1 R40.2 R43.1 R61.1 U1.6 U2.6 U5.6 U7.6 U8.6 U10.6 U12.6 U14.6 | length 199.9
  Top Layer w0.152: U8.6@6.139,33.104 U8.6@6.212,33.177 ; U14.6@8.969,33.104 U14.6@9.042,33.177
  Top Layer w0.254: v2(5.461,33.147) 6.096,33.147 U8.6@6.139,33.104 ; v1@8.255,33.147 8.926,33.147 U14.6@8.969,33.104 ; v2(32.425,33.165) 32.49,33.231 U2.6@32.756,33.231 ; v1(34.998,33.149) 35.536,33.149 35.539,33.147 35.587,33.195 U1.6@35.587,33.231 ; v2(37.676,33.631) 37.811,33.496 38.417,33.496 U5.6@38.417,33.231 ; v2@40.861,33.683 41.12,33.683 41.247,33.556 U10.6@41.247,33.231
  Top Layer w0.305: 12.421,89.855 15.392,92.827 R40.2@15.392,92.964 ; v1(27.254,94.31) R61.1@30.25,94.31
  Top Layer w0.381: v2(2.413,33.02) 1.333,31.94 1.333,29.585 2.618,28.301 3.389,28.301 4.585,27.104 4.585,24.637 5.601,23.621 5.601,23.189 R15.2@5.803,22.987 R15.2@5.848,23.032 ; v2@2.429,33.004 U7.6@3.235,33.004 ; 8.587,23.032 8.689,22.93 ; R17.2@8.689,22.2 8.689,22.93 ; 8.689,23.661 8.689,22.93 ; v1(11.031,34.367) 11.756,33.642 11.756,33.147 U12.6@11.799,33.104
  Top Layer w0.508: K2.2@2.108,91.669 K2.1@9.677,91.669 10.607,91.669 12.421,89.855 12.624,89.652 v1(12.624,87.224) ; R15.2@5.848,23.032 8.587,23.032 ; v8(13.369,45.021) 25.183,45.021 CN5.1@28.421,41.783
  Bottom Layer w0.305: 24.689,86.969 24.689,91.745 v1(27.254,94.31)
  Bottom Layer w0.381: v2(2.413,33.02) 2.509,33.02 2.633,33.144 C15.2@4.289,33.144 ; C15.2@4.318,33.115 C15.2@4.289,33.144 ; v2@5.458,33.144 C15.2@4.289,33.144 ; v2(5.461,33.147) v1(8.224,33.147) 9.728,33.147 9.931,33.35 R23.2@9.931,34.367 ; v1(11.031,34.367) R23.2@9.931,34.367 ; CN1.1@28.321,35.052 26.187,37.186 9.246,37.186 8.636,36.576 8.636,35.579 9.671,34.544 R23.2@9.931,34.544 R23.2@9.931,34.367 ; v2(32.425,33.165) 34.982,33.165 v1@34.982,33.103 ; v1@34.992,33.149 v1(34.998,33.149) 35.461,33.149 36.142,33.831 40.591,33.831 v2(40.64,33.782)
  Bottom Layer w0.508: JP4.1@6.477,41.391 11.711,46.625 ; 9.677,48.659 11.711,46.625 ; 9.677,48.71 9.677,84.277 v1(12.624,87.224) 24.251,87.224 R43.1@24.689,86.785 ; v8(13.369,45.021) 13.316,45.021 11.711,46.625 ; CN1.1@28.421,35.152 CN5.1@28.421,41.783 34.798,41.783 JP2.1@34.925,41.91 34.925,43.282 35.255,43.612 ; CN1.1@28.5,35.262 29.044,34.798 35.227,34.798 36.142,33.883 36.142,33.831
TVDD*: JP1.2 R34.1 | length 3.3
  Top Layer w0.508: JP1.2@8.509,26.162 8.629,26.162 10.213,24.578 10.213,23.661
TVDD_DISCHARGE_EN: R19.2 U15.25 | length 10.3
  Top Layer w0.152: R19.2@10.199,19.933 11.392,19.933 11.874,20.415 11.874,21.858 13.578,23.562 15.332,23.562 16.332,22.562 U15.25@17.721,22.562
USB_DM: R11.2 U15.32 | length 13.6
  Top Layer w0.152: R11.2@6.35,13.589 7.782,15.021 11.64,15.021 15.681,19.062 U15.32@17.721,19.062
USB_DP: R12.2 U15.33 | length 12
  Top Layer w0.152: R12.2@7.81,13.589 8.749,14.528 11.982,14.528 16.016,18.562 U15.33@17.721,18.562
VBUS_PYLK: F1.1 PYLK.A4 PYLK.A9 PYLK.B4 PYLK.B9 U6.5 | length 20.5
  Top Layer w0.254: PYLK.A4@19.68,7.871 PYLK.B9@19.98,7.871 ; PYLK.B4@24.48,7.871 PYLK.A9@24.78,7.871
  Top Layer w0.508: U6.5@14.431,7.874 14.452,7.853 15.483,7.853 v2(15.499,7.837) ; PYLK.B9@19.839,8.32 v4@19.839,9.435 ; PYLK.B4@24.618,8.341 v4@24.618,9.2
  Bottom Layer w0.381: F1.1@12.649,10.617 13.126,10.14 13.126,9.811 15.076,7.86 15.476,7.86 v2(15.499,7.837)
  Bottom Layer w0.508: v4@24.819,9.449 v4(24.832,9.461)
  Bottom Layer w0.762: F1.1@12.649,10.668 18.605,10.668 v4(19.812,9.461) ; v4@19.825,9.449 23.512,9.449 ; 23.512,9.485 v4@24.809,9.485
VCCA: C28.2 C29.2 CN3.13 L1.2 U18.13 | length 27.5
  Top Layer w0.254: U18.13@24.46,62.959 24.46,60.699 24.913,60.246 39.226,60.246 39.856,59.615 41.958,59.615 CN3.13@43.17,60.827 ; U18.13@24.468,62.967 24.468,64.276 v1(24.791,64.599)
  Bottom Layer w0.381: v1(24.791,64.599) 24.791,66.676 C28.2@24.994,66.878 26.378,66.878 L1.2@26.429,66.929
VDD: C27.2 CN3.32 J1.1 J1.2 JP2.2 L1.1 R37.2 U18.32 | length 67.4
  Top Layer w0.305: U18.32@27.409,72.495 28.845,72.495 29.653,73.303 29.653,73.77 31.372,75.489 C27.2@31.488,75.489
  Top Layer w0.381: C27.2@31.488,75.489 33.579,75.489 v1(33.604,75.514) ; JP2.2@37.516,41.91 JP2.2@37.79,42.184
  Bottom Layer w0.381: R37.2@36.729,43.663 37.465,42.927 JP2.2@37.465,41.91
  Bottom Layer w0.508: L1.1@28.029,66.929 33.604,66.929 ; 36.741,43.84 35.204,45.377 35.204,65.329 33.604,66.929 ; J1.1@43.18,87.63 J1.2@40.64,87.63 40.63,87.62 CN3.32@40.63,83.687 38.733,83.687 33.604,78.558 v1(33.604,75.514) 33.604,66.929
VSSA: C28.1 C29.1 C36.1 CN3.12 R50.1 U18.12 | length 27.4
  Top Layer w0.254: v1(23.642,64.589) 23.968,64.263 U18.12@23.968,62.967 23.968,60.392 24.589,59.771 38.59,59.771 CN3.12@40.074,58.287
  Top Layer w0.305: CN3.12@40.074,58.287 CN3.12@40.63,58.287
  Bottom Layer w0.381: C36.1@23.19,63.398 23.642,63.85 v1(23.642,64.589) 23.642,65.385 C29.1@23.419,65.608 C28.1@23.419,66.878 23.419,67.462 R50.1@24.257,68.301
pads on no net: PYLK. PYLK.A8 PYLK.B8 U15.42 U15.45

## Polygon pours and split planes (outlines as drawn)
GND on Top Layer "NONET_L-01_P-001" (solid, remove dead copper, pour order 4): 0.127,98.171 44.958,98.171 44.958,0 -0.089,0
GND on Bottom Layer "NONET_L-01_P-001" (solid, remove dead copper, pour order 3): 0.127,98.171 44.958,98.171 44.958,0 -0.089,0

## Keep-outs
Keep-Out Layer:
  lines w0.152: 0,2 0,37.338 ; 0,41.021 0,96 ; 1.079,38.481 3.619,38.481 ; 1.079,39.878 3.619,39.878 ; 2,0 43,0 ; 2,98.198 43,98.198 ; 5.461,38.481 14.351,38.481 14.859,38.481 ; 5.461,39.878 14.351,39.878 14.859,39.878 ; 32.004,38.481 32.512,38.481 39.624,38.481 ; 32.004,39.878 32.512,39.878 39.624,39.878 ; 41.402,38.481 43.942,38.481 ; 41.402,39.878 43.942,39.878 ; 45,2 45,37.423 ; 45,40.936 45,96
  lines w0.203: 0,2 ccw(c2,2) 2,0 ; 0,37.338 cw(c1.111,37.37) 1.079,38.481 ; 0,41.021 ccw(c1.111,40.989) 1.079,39.878 ; 0,96 cw(c2.099,96.099) 2,98.198 ; 3.62,38.481 ccw(c2.921,39.179) 3.62,39.878 ; 5.461,38.481 cw(c6.159,39.179) 5.461,39.878 ; 14.859,38.481 ccw(c14.16,39.179) 14.859,39.878 ; 32.004,38.481 cw(c32.703,39.179) 32.004,39.878 ; 39.624,38.481 ccw(c38.925,39.179) 39.624,39.878 ; 41.402,38.481 cw(c42.1,39.179) 41.402,39.878 ; 43,0 ccw(c43,2) 45,2 ; 43,98.198 cw(c42.901,96.099) 45,96 ; 43.942,38.481 cw(c43.942,37.423) 45,37.423 ; 43.942,39.878 ccw(c43.942,40.936) 45,40.936

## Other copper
Top Layer:
  pour cut-out: 42.037,34.798 42.291,34.798 42.291,34.544 42.037,34.544
  pour cut-out: 6.985,12.446 7.239,12.446 7.239,12.192 6.985,12.192
  pour cut-out: 6.985,13.335 7.239,13.335 7.239,13.081 6.985,13.081
  pour cut-out: 8.382,13.335 8.522,13.335 8.522,12.776 8.382,12.776
  pour cut-out: 8.382,12.446 8.636,12.446 8.636,12.192 8.382,12.192
  region net 5V_USB_CHGR: 9.779,5.969 10.033,6.223 10.668,6.223 11.811,5.08 12.954,5.08 13.462,4.572 16.764,4.572 16.764,3.048 13.081,3.048 13.081,3.556 12.446,4.191 11.049,4.191 10.16,5.08 9.779,5.461
  region net 3V3_PYLK: 6.096,8.001 7.366,8.001 7.874,7.493 9.017,7.493 9.144,7.366 9.144,6.35 8.763,5.969 8.763,4.191 9.207,3.746 9.017,3.556 7.452,3.556 7.452,3.899 7.747,4.193 7.747,5.842 7.112,6.477 6.096,6.477
  region net 3V3_PYLK: 27.813,3.937 28.067,4.191 28.575,4.191 28.829,3.937 28.829,3.302 28.956,3.175 30.099,3.175 30.226,3.048 30.226,2.667 30.099,2.54 28.702,2.54 27.813,3.429
  region net 3V3_USB_PYLK: 31.178,3.048 33.02,3.048 33.401,3.429 33.909,3.429 34.163,3.175 34.163,2.667 33.782,2.286 33.401,2.286 32.766,1.651 32.766,0.635 31.115,0.635 31.115,3.006
  pour cut-out: 9.906,12.573 10.16,12.573 10.16,12.319 9.906,12.319
  pour cut-out: 11.303,12.573 11.557,12.573 11.557,12.319 11.303,12.319
  pour cut-out: 41.337,26.34 41.591,26.34 41.591,26.086 41.337,26.086
  pour cut-out: 42.545,27.305 42.799,27.305 42.799,27.051 42.545,27.051
Bottom Layer:
  pour cut-out: 27.102,66.149 27.102,67.709 27.348,67.709 27.348,66.149
  pour cut-out: 24.087,65.007 24.087,67.429 24.333,67.429 24.333,65.007

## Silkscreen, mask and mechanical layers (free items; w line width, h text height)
Top Overlay:
  drawing of 1057 lines, arcs and shapes, not listed
  text "USER_PB0" at 3.023,89.252 h1.27
  text "NRST" at 37.541,89.143 h1.27
  text "GND" at 5.842,87.288 h1.27
  text "GND" at 9.017,87.288 h1.27
  text "VDD" at 33.267,87.274 h1.27
  text "VDD" at 36.476,87.274 h1.27
  text "33" at 1.067,85.282 h1.27
  text "34" at 3.658,85.282 h1.27
  text "32" at 40.056,85.129 h1.27
  text "31" at 42.647,85.129 h1.27
  text "PB13" at 9.017,83.326 h1.27
  text "PB12" at 5.715,83.312 h1.27
  text "GND" at 36.618,83.25 h1.27
  text "VDD" at 33.267,83.236 h1.27
  text "PB14" at 5.715,80.782 h1.27
  text "PB15" at 9.017,80.781 h1.27
  text "PB11" at 33.118,80.71 h1.27
  text "PB10" at 36.384,80.709 h1.27
  text "PY32F420-START V2.0" at 16.383,78.847 h1.65
  text "PC6" at 5.715,78.228 h1.27
  text "PC7" at 9.017,78.224 h1.27
  text "PB2" at 33.601,78.184 h1.27
  text "PB1" at 37.17,78.182 h1.27
  text "2026-02" at 20.953,76.695 h1.65
  text "PC8" at 5.715,75.673 h1.27
  text "PC9" at 9.017,75.668 h1.27
  text "PB0" at 33.595,75.644 h1.27
  text "PC5" at 36.945,75.63 h1.27
  text "PA8" at 5.715,73.13 h1.27
  text "PA9" at 9.017,73.123 h1.27
  text "PC4" at 33.534,73.094 h1.27
  text "PA7" at 37.013,73.107 h1.27
  text "PA10" at 5.715,70.586 h1.27
  text "PA11" at 9.017,70.592 h1.27
  text "PA6" at 33.592,70.554 h1.27
  text "PA5" at 37.007,70.569 h1.27
  text "PA12" at 5.715,68.056 h1.27
  text "PA13" at 9.017,68.046 h1.27
  text "PA4" at 33.596,68.031 h1.27
  text "PD5" at 36.945,68.031 h1.27
  text "PD6" at 5.715,65.512 h1.27
  text "PD7" at 9.017,65.518 h1.27
  text "PD4" at 33.534,65.509 h1.27
  text "PA3" at 37.013,65.49 h1.27
  text "PA14" at 5.715,62.982 h1.27
  text "PA2" at 33.601,62.983 h1.27
  text "PA15" at 9.017,62.973 h1.27
  text "PA1" at 37.17,62.963 h1.27
  text "VCCA" at 36.222,60.466 h1.27
  text "PA0" at 33.595,60.443 h1.27
  text "PC10" at 5.715,60.428 h1.27
  text "PC11" at 9.017,60.417 h1.27
  text "PD2" at 9.017,57.885 h1.27
  text "VSSA" at 33.198,57.893 h1.27
  text "PC3" at 36.951,57.888 h1.27
  text "PC12" at 5.715,57.873 h1.27
  text "PB4" at 9.017,55.357 h1.27
  text "PC2" at 33.538,55.342 h1.27
  text "PC1" at 37.108,55.336 h1.27
  text "PB3" at 5.715,55.33 h1.27
  text "PB6" at 9.017,52.812 h1.27
  text "PD11" at 36.477,52.809 h1.27
  text "PB5" at 5.715,52.789 h1.27
  text "PC0" at 33.533,52.792 h1.27
  text "PB7" at 5.715,50.263 h1.27
  text "PD3" at 9.017,50.266 h1.27
  text "PD1" at 33.687,50.266 h1.27
  text "PD0" at 36.953,50.268 h1.27
  text "PB8" at 5.715,47.719 h1.27
  text "PB9" at 9.017,47.721 h1.27
  text "PC15" at 32.893,47.715 h1.27
  text "PC14" at 36.323,47.716 h1.27
  text "PD8" at 5.715,45.175 h1.27
  text "PD9" at 9.017,45.175 h1.27
  text "PD10" at 36.322,45.175 h1.27
  text "PC13" at 32.899,45.165 h1.27
  text "VDD*" at 27.941,43.447 h1.14
  text "63" at 1.041,43.423 h1.27
  text "64" at 3.658,43.423 h1.27
  text "NRST" at 16.002,43.447 h1.14
  text "SWC" at 19.304,43.447 h1.14
  text "GND" at 22.098,43.447 h1.14
  text "SWD" at 25.019,43.447 h1.14
  text "1" at 42.977,43.282 h1.27
  text "2" at 40.336,43.25 h1.27
  text "VDD*" at 33.631,43.18 h1.14
  text "VDD" at 36.552,43.18 h1.14
  text "GND" at 0.152,42.608 h1.14
  text "BOOT0" at 2.667,42.608 h1.14
  text "VDD" at 6.351,42.57 h1.14
  text "BOOT_SEL" at 8.001,41.478 h1.14
  text "IDD" at 38.788,41.458 h1.27
  text "NRST" at 17.018,36.714 h1.02
  text "SWC" at 20.066,36.714 h1.02
  text "GND" at 22.78,36.714 h1.02
  text "SWD" at 25.306,36.714 h1.02
  text "VDD*" at 27.687,36.715 h1.02
  text "DTR" at 22.78,29.867 h1.02
  text "TX" at 25.306,29.867 h1.02
  text "RX" at 27.686,29.867 h1.02
  text "SWO" at 17.018,29.856 h1.02
  text "RTS" at 20.066,29.856 h1.02
  text "VDD_SEL" at 13.031,27.432 h1.14
  text "5V" at 4.826,27.322 h1.52
  text "3V3" at 10.414,27.322 h1.52
  text "VDD*" at 6.732,27.305 h1.52
  text "BT0" at 28.891,10.643 h1.27 r90
  text "VDD" at 31.404,10.644 h1.27 r90
  text "DIO" at 33.944,10.643 h1.27 r90
  text "GND" at 36.485,10.643 h1.27 r90
  text "CLK" at 39.026,10.643 h1.27 r90
  text "PY-LINK OB V2.1" at 15.291,9.81 h1.65
Bottom Overlay:
Mechanical 1:
  lines w0.152: 5.461,38.481 14.351,38.481 14.859,38.481 ; 5.461,39.878 14.351,39.878 14.859,39.878 ; 32.004,38.481 32.512,38.481 39.624,38.481 ; 32.004,39.878 32.512,39.878 39.624,39.878
  lines w0.203: 5.461,38.481 cw(c6.159,39.179) 5.461,39.878 ; 14.859,38.481 ccw(c14.16,39.179) 14.859,39.878 ; 32.004,38.481 cw(c32.703,39.179) 32.004,39.878 ; 39.624,38.481 ccw(c38.925,39.179) 39.624,39.878

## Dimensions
1.079,39.878 to 2,98.198 on Mechanical 1
45,2 to 46.609,98.171 on Mechanical 1
2,0 to -0.127,38.227 on Mechanical 1
0,0 to 44.958,-1.524 on Mechanical 1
